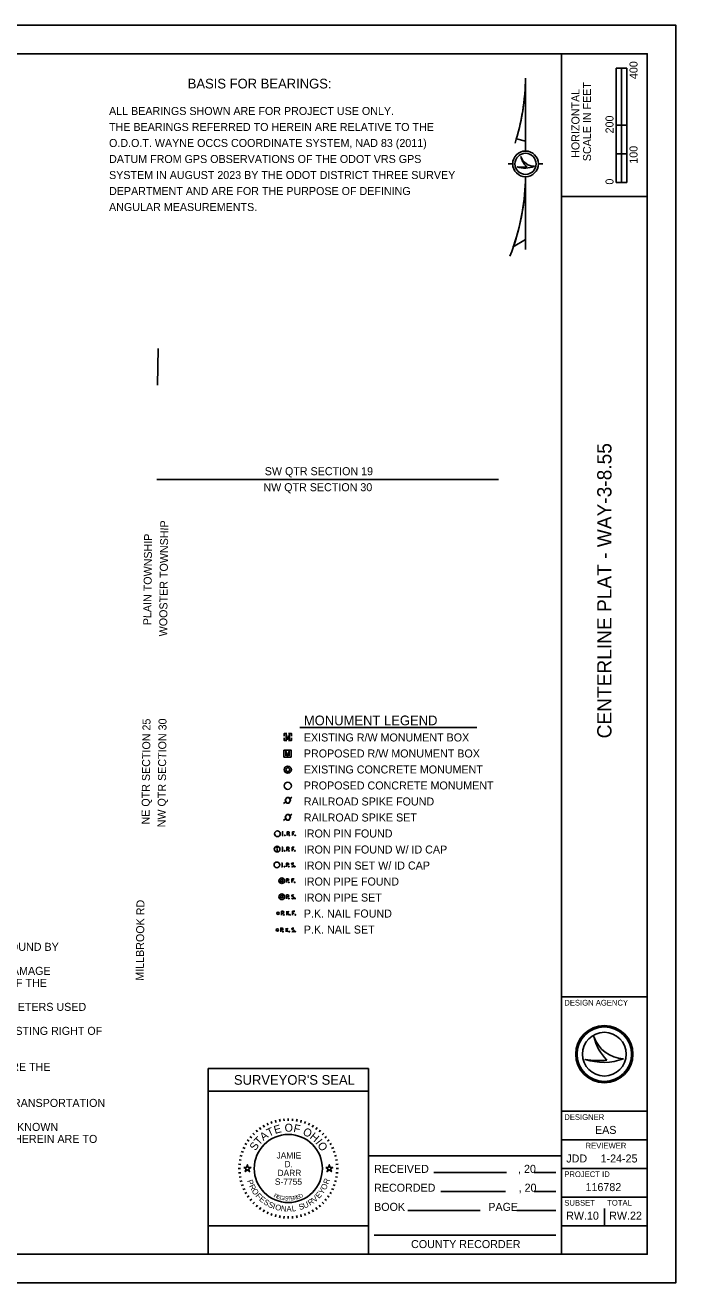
# Model space of a CAD drawing. Extents: x 132828 to 139628, y 472735 to 477135.
# Drawn here: x 137353 to 139628, y 472735 to 477135 of the extents above; entities that cross this region are included whole.
import ezdxf

# ---------------------------------------------------------------- set-up
doc = ezdxf.new("R2010")
doc.units = 0
for name, color, linetype in [('_CIVIL_CONSTRUCTION', 7, 'Continuous'), ('Default', 7, 'Continuous'), ('GE_X_Alignment', 7, 'Continuous'), ('GE_X_Alignment_100_Bearings', 7, 'Continuous'), ('GE_X_Alignment_100_Cardinal_Points', 7, 'Continuous'), ('GE_X_Alignment_100_Stations', 7, 'Continuous')]:
    doc.layers.add(name, color=color, linetype=linetype)

msp = doc.modelspace()

# ---------------------------------------------------------------- linework, layer by layer
at = {"layer": '_CIVIL_CONSTRUCTION'}
msp.add_lwpolyline([(132828.1, 472735.2), (139628.1, 472735.2), (139628.1, 477135.2), (132828.1, 477135.2)], close=True, dxfattribs=at)
at = {"layer": 'Default'}
for p, q in [((138257.6, 473309.5), (138258.3, 473301.5)), ((138272.9, 473310.2), (138272.9, 473302.2)), ((138288.1, 473309.5), (138287.4, 473301.5)), ((138160.4, 473269.2), (138165.5, 473263.1)), ((138172.5, 473278.5), (138177.1, 473272)), ((138185.4, 473286.7), (138189.4, 473279.8)), ((138198.9, 473293.8), (138202.3, 473286.5)), ((138213, 473299.6), (138215.8, 473292.1)), ((138227.6, 473304.2), (138229.7, 473296.5)), ((138242.5, 473307.5), (138243.9, 473299.6)), ((138303.3, 473307.5), (138301.9, 473299.6)), ((138318.2, 473304.2), (138316.1, 473296.5)), ((138332.7, 473299.6), (138330, 473292.1)), ((138346.9, 473293.8), (138343.5, 473286.5)), ((138360.4, 473286.7), (138356.4, 473279.8)), ((138373.3, 473278.5), (138368.7, 473272)), ((138385.4, 473269.2), (138380.2, 473263.1)), ((138121.3, 473222.7), (138128.3, 473218.7)), ((138129.5, 473235.5), (138136.1, 473231)), ((138138.8, 473247.7), (138145, 473242.5)), ((138149.1, 473258.9), (138154.8, 473253.3)), ((138396.6, 473258.9), (138391, 473253.3)), ((138407, 473247.7), (138400.8, 473242.5)), ((138416.2, 473235.5), (138409.7, 473231)), ((138424.4, 473222.7), (138417.5, 473218.7)), ((138103.9, 473180.5), (138111.6, 473178.4)), ((138108.4, 473195), (138116, 473192.3)), ((138114.3, 473209.1), (138121.5, 473205.7)), ((138431.5, 473209.1), (138424.2, 473205.7)), ((138437.3, 473195), (138429.8, 473192.3)), ((138441.9, 473180.5), (138434.2, 473178.4)), ((138097.9, 473135.2), (138105.9, 473135.2)), ((138098.6, 473150.4), (138106.5, 473149.7)), ((138100.6, 473165.6), (138108.4, 473164.2)), ((138445.2, 473165.6), (138437.4, 473164.2)), ((138447.2, 473150.4), (138439.3, 473149.7)), ((138447.9, 473135.2), (138439.9, 473135.2)), ((138098.6, 473119.9), (138106.5, 473120.6)), ((138100.6, 473104.8), (138108.4, 473106.2)), ((138103.9, 473089.9), (138111.6, 473091.9)), ((138441.9, 473089.9), (138434.2, 473091.9)), ((138445.2, 473104.8), (138437.4, 473106.2)), ((138447.2, 473119.9), (138439.3, 473120.6)), ((138108.4, 473075.3), (138116, 473078)), ((138114.3, 473061.2), (138121.5, 473064.6)), ((138121.3, 473047.7), (138128.3, 473051.7)), ((138424.4, 473047.7), (138417.5, 473051.7)), ((138431.5, 473061.2), (138424.2, 473064.6)), ((138437.3, 473075.3), (138429.8, 473078)), ((138129.5, 473034.8), (138136.1, 473039.4)), ((138138.8, 473022.7), (138145, 473027.8)), ((138149.1, 473011.4), (138154.8, 473017.1)), ((138160.4, 473001.1), (138165.5, 473007.2)), ((138385.4, 473001.1), (138380.2, 473007.2)), ((138396.6, 473011.4), (138391, 473017.1)), ((138407, 473022.7), (138400.8, 473027.8)), ((138416.2, 473034.8), (138409.7, 473039.4)), ((138172.5, 472991.8), (138177.1, 472998.4)), ((138185.4, 472983.6), (138189.4, 472990.5)), ((138198.9, 472976.6), (138202.3, 472983.8)), ((138213, 472970.7), (138215.8, 472978.2)), ((138227.6, 472966.1), (138229.7, 472973.9)), ((138242.5, 472962.8), (138243.9, 472970.7)), ((138257.6, 472960.8), (138258.3, 472968.8)), ((138272.9, 472960.2), (138272.9, 472968.2)), ((138288.1, 472960.8), (138287.4, 472968.8)), ((138303.3, 472962.8), (138301.9, 472970.7)), ((138318.2, 472966.1), (138316.1, 472973.9)), ((138332.7, 472970.7), (138330, 472978.2)), ((138346.9, 472976.6), (138343.5, 472983.8)), ((138360.4, 472983.6), (138356.4, 472990.5)), ((138373.3, 472991.8), (138368.7, 472998.4))]:
    msp.add_line(p, q, dxfattribs=at)
for points in [[(138117.6, 473139.2), (138127, 473139.2), (138129.9, 473148.1), (138132.8, 473139.2), (138142.2, 473139.2), (138134.6, 473133.6), (138137.5, 473124.7), (138129.9, 473130.2), (138122.3, 473124.7), (138125.2, 473133.6)], [(138403.6, 473139.2), (138413, 473139.2), (138415.9, 473148.1), (138418.8, 473139.2), (138428.2, 473139.2), (138420.6, 473133.6), (138423.5, 473124.7), (138415.9, 473130.2), (138408.3, 473124.7), (138411.2, 473133.6)]]:
    msp.add_lwpolyline(points, close=True, dxfattribs=at)
msp.add_circle((138272.9, 473135.2), 119, dxfattribs=at)
at = {"layer": 'GE_X_Alignment'}
for p, q in [((138313.4, 474678.2), (138931.9, 474678.2)), ((138271, 474644.9), (138271, 474644.9)), ((138270, 474586.8), (138270, 474586.8)), ((138264.3, 474418.5), (138256.3, 474412.5)), ((138285.7, 474434.5), (138277.7, 474428.5)), ((138285.7, 474375.1), (138277.7, 474369.1)), ((138264.3, 474359.1), (138256.3, 474353.2)), ((138251.3, 474313), (138254.6, 474313)), ((138251.3, 474313), (138254.6, 474313)), ((138251.3, 474299.7), (138254.6, 474299.7)), ((138252.9, 474299.7), (138252.9, 474313)), ((138268.3, 474306.6), (138273.6, 474306.6)), ((138287, 474299.7), (138287, 474313)), ((138287, 474313), (138294.7, 474313)), ((138287, 474306.5), (138292.5, 474306.5)), ((138233.8, 474253.5), (138233.8, 474246.1)), ((138250.4, 474259.2), (138253.8, 474259.2)), ((138250.4, 474259.2), (138253.8, 474259.2)), ((138250.4, 474245.8), (138253.8, 474245.8)), ((138252.1, 474245.8), (138252.1, 474259.2)), ((138267.4, 474252.8), (138272.8, 474252.8)), ((138286.2, 474245.8), (138286.2, 474259.2)), ((138286.2, 474259.2), (138293.8, 474259.2)), ((138286.2, 474252.7), (138291.6, 474252.7)), ((138249.6, 474203.9), (138252.9, 474203.9)), ((138249.6, 474203.9), (138252.9, 474203.9)), ((138249.6, 474190.5), (138252.9, 474190.5)), ((138251.2, 474190.5), (138251.2, 474203.9)), ((138266.6, 474197.5), (138271.9, 474197.5)), ((138285.4, 474199.1), (138291.5, 474196)), ((138285.5, 474135.4), (138285.5, 474148.7)), ((138285.5, 474148.7), (138293.2, 474148.7)), ((138266.8, 474142.3), (138272.1, 474142.3)), ((138285.5, 474142.2), (138291, 474142.2)), ((138266.8, 474086.1), (138272.1, 474086.1)), ((138285.7, 474087.7), (138291.8, 474084.5)), ((138249.2, 474028.6), (138254.5, 474028.6)), ((138267.9, 474021.7), (138267.9, 474035)), ((138267.9, 474026.5), (138274.3, 474035)), ((138269.9, 474029.3), (138275.4, 474021.7)), ((138287.5, 474021.7), (138287.5, 474035)), ((138287.5, 474035), (138295.2, 474035)), ((138287.5, 474028.5), (138293, 474028.5)), ((138246.3, 473970), (138251.7, 473970)), ((138264.9, 473963.1), (138264.9, 473976.4)), ((138264.9, 473967.9), (138271.3, 473976.4)), ((138266.9, 473970.7), (138272.4, 473963.1)), ((138286, 473971.8), (138292.1, 473968.6)), ((138552.9, 472835.2), (138552.9, 473180)), ((138552.9, 473180), (139228.1, 473180)), ((139228.1, 473180), (139228.1, 472835.2)), ((138781.4, 473121), (139035.9, 473121)), ((139132.6, 473121), (139208.1, 473121)), ((138806.5, 473054.3), (139032.7, 473054.3)), ((139132.6, 473054.3), (139208.1, 473054.3)), ((138690.8, 472987.7), (138944, 472987.7)), ((139072, 472987.7), (139208.1, 472987.7)), ((138572.9, 472902), (139208.1, 472902))]:
    msp.add_line(p, q, dxfattribs=at)
for points in [[(138258.5, 474648.1), (138258.5, 474657.4), (138267.8, 474657.4)], [(138267.8, 474632.4), (138258.5, 474632.4), (138258.5, 474641.8)], [(138264.8, 474636.6), (138264.8, 474653.2), (138271, 474636.6), (138277.1, 474653.2), (138277.1, 474636.6)], [(138273.9, 474657.4), (138283.5, 474657.4), (138283.5, 474648.1)], [(138283.5, 474641.8), (138283.5, 474632.4), (138273.9, 474632.4)], [(138257.5, 474599.3), (138282.6, 474599.3), (138282.6, 474574.3), (138257.5, 474574.3), (138257.5, 474599.3)], [(138263.9, 474578.5), (138263.9, 474595.1), (138270, 474578.5), (138276.2, 474595.1), (138276.2, 474578.5)], [(138273.6, 474313), (138268.3, 474313), (138268.3, 474299.7)], [(138272.8, 474259.2), (138267.4, 474259.2), (138267.4, 474245.8)], [(138271.9, 474203.9), (138266.6, 474203.9), (138266.6, 474190.5)], [(138272.1, 474148.7), (138266.8, 474148.7), (138266.8, 474135.4)], [(138272.1, 474092.4), (138266.8, 474092.4), (138266.8, 474079.1)], [(138254.5, 474035), (138249.2, 474035), (138249.2, 474021.7)], [(138251.7, 473976.4), (138246.3, 473976.4), (138246.3, 473963.1)]]:
    msp.add_lwpolyline(points, dxfattribs=at)
for points in [[(138267.2, 474433.5), (138274.7, 474433.5), (138280.6, 474423.5), (138274.7, 474413.5), (138267.2, 474413.5), (138261.3, 474423.5)], [(138267.2, 474374.1), (138274.7, 474374.1), (138280.6, 474364.1), (138274.7, 474354.1), (138267.2, 474354.1), (138261.3, 474364.1)]]:
    msp.add_lwpolyline(points, close=True, dxfattribs=at)
for centre, radius in [((138271, 474530.4), 12.5), ((138271, 474530.4), 6.67), ((138271, 474474.1), 12.5), ((138234.6, 474306.3), 10), ((138261, 474300.6), 1.17), ((138276.3, 474300.6), 1.17), ((138296.6, 474300.6), 1.17), ((138233.8, 474252.5), 10), ((138233.8, 474257.9), 1.33), ((138260.1, 474246.7), 1.17), ((138275.4, 474246.7), 1.17), ((138295.8, 474246.7), 1.17), ((138232.9, 474197.2), 10), ((138259.3, 474191.4), 1.17), ((138274.6, 474191.4), 1.17), ((138296, 474191.4), 1.17), ((138250.1, 474142.1), 10), ((138250.1, 474142.1), 4.12), ((138274.8, 474136.3), 1.17), ((138295.2, 474136.3), 1.17), ((138250.1, 474085.8), 10), ((138250.1, 474085.8), 4.17), ((138274.8, 474080), 1.17), ((138296.2, 474079.9), 1.17), ((138237.2, 474028.3), 4.15), ((138257.2, 474022.6), 1.17), ((138279.1, 474022.6), 1.17), ((138297.2, 474022.6), 1.17), ((138234.6, 473969.8), 4.12), ((138254.3, 473964), 1.17), ((138276.6, 473964), 1.17), ((138296.6, 473964), 1.17)]:
    msp.add_circle(centre, radius, dxfattribs=at)
for centre, radius, start, end in [((138273.1, 474309.8), 3.24, 278.8803, 81.1197), ((138272.3, 474256), 3.24, 278.8803, 81.1197), ((138271.4, 474200.7), 3.24, 278.8803, 81.1197), ((138286.7, 474201.1), 2.37, 126.2587, 236.3675), ((138288.4, 474196.1), 5.53, 223.6695, 304.3963), ((138288.7, 474196.9), 6.99, 61.3463, 118.6537), ((138289.5, 474193.8), 2.96, 311.4883, 47.9358), ((138271.6, 474145.5), 3.24, 278.8803, 81.1197), ((138271.6, 474089.2), 3.24, 278.8803, 81.1197), ((138287, 474089.7), 2.37, 126.2587, 236.3675), ((138288.6, 474084.7), 5.53, 223.6695, 304.3963), ((138288.9, 474085.4), 6.99, 61.3463, 118.6537), ((138289.8, 474082.3), 2.96, 311.4883, 47.9358), ((138254, 474031.8), 3.24, 278.8803, 81.1197), ((138251.2, 473973.2), 3.24, 278.8803, 81.1197), ((138287.3, 473973.7), 2.37, 126.2587, 236.3675), ((138289.3, 473969.5), 6.99, 61.3463, 118.6537), ((138290.1, 473966.4), 2.96, 311.4883, 47.9358), ((138289, 473968.7), 5.53, 223.6695, 304.3963)]:
    msp.add_arc(centre, radius, start, end, dxfattribs=at)
at = {"layer": 'GE_X_Alignment_100_Bearings'}
for p, q in [((139419.5, 476585.2), (139419.5, 476985.2)), ((139457, 476985.2), (139419.5, 476985.2)), ((139419.5, 476785.2), (139419.5, 476985.2)), ((139419.5, 476985.2), (139438.1, 476985.2)), ((139438.1, 476985.2), (139438.3, 476985.2)), ((139438.3, 476985.2), (139438.3, 476785.2)), ((139457, 476985.2), (139457, 476585.2)), ((139102.5, 476694.8), (139102.5, 476949.8)), ((139438.3, 476785.2), (139419.5, 476785.2)), ((139456.8, 476785.2), (139438.1, 476785.2)), ((139438.1, 476785.2), (139438.1, 476685.2)), ((139456.8, 476685.2), (139456.8, 476785.2)), ((139070.6, 476737.9), (139102.5, 476729.2)), ((139438.1, 476685.2), (139419.5, 476685.2)), ((139419.5, 476685.2), (139419.5, 476585.2)), ((139438.1, 476685.2), (139456.8, 476685.2)), ((139438.1, 476585.2), (139438.1, 476685.2)), ((139041.5, 476649.8), (139057.5, 476649.8)), ((139147.5, 476649.8), (139163.5, 476649.8)), ((139102.5, 476349.8), (139102.5, 476604.8)), ((139457, 476585.2), (139419.5, 476585.2)), ((139419.5, 476585.2), (139438.1, 476585.2)), ((139102.5, 476384.8), (139059.6, 476359.1)), ((139341.6, 473597.1), (139341.6, 473597.1)), ((139378.1, 473535.2), (139378.1, 473535.2)), ((138552.9, 473485.2), (137992.9, 473485.2)), ((137992.9, 473485.2), (137992.9, 472835.2)), ((138552.9, 472835.2), (138552.9, 473485.2)), ((139311.6, 473517.1), (139311.6, 473517.1)), ((139445.6, 473518.9), (139445.6, 473518.9)), ((138552.9, 473405.2), (137992.9, 473405.2)), ((139378.1, 472935.2), (139378.1, 472995.2)), ((138552.9, 472835.2), (137992.9, 472835.2))]:
    msp.add_line(p, q, dxfattribs=at)
for points in [[(139070.4, 476738), (139070.6, 476737.9), (139102.5, 476729.2), (139102.5, 476949.8)], [(139059.6, 476359.1), (139102.5, 476384.8), (139102.5, 476604.8)]]:
    msp.add_lwpolyline(points, dxfattribs=at)
msp.add_lwpolyline([(138552.9, 472835.2), (138552.9, 472935.2), (137992.9, 472935.2), (137992.9, 472835.2)], close=True, dxfattribs=at)
for centre, radius in [((139102.5, 476649.8), 45), ((139102.5, 476649.8), 37), ((139378.1, 473535.2), 100), ((139378.1, 473535.2), 95.4), ((139378.1, 473535.2), 95.4), ((139378.1, 473535.2), 76.4)]:
    msp.add_circle(centre, radius, dxfattribs=at)
for centre, radius, start, end in [((138314.1, 476960.9), 788.5, 342.4153, 359.1947), ((138314.1, 476960.9), 788.5, 343.5754, 359.1947), ((139134, 476692.4), 51, 199.1575, 269.3709), ((139155.8, 476691.6), 71.7, 192.8556, 227.3141), ((139100.3, 476725.6), 90.5, 252.4874, 291.486), ((139091.5, 476752.1), 114.3, 260.7277, 277.8734), ((138314.1, 476615.9), 788.5, 338.5054, 359.1947), ((138314.1, 476615.9), 788.5, 340.9936, 359.1947), ((139451.3, 473634.7), 116, 198.9257, 198.9319), ((139497.5, 473629.2), 159.1, 191.6379, 191.6421), ((139451.3, 473634.7), 116, 198.9319, 267.1657), ((139497.5, 473629.2), 159.1, 191.6421, 226.0947), ((139376, 473709.2), 202.6, 251.4576, 290.0832), ((139357.7, 473766), 253.2, 259.4964, 259.4995), ((139376, 473709.2), 202.6, 251.4527, 251.4576), ((139357.7, 473766), 253.2, 259.4995, 276.6672)]:
    msp.add_arc(centre, radius, start, end, dxfattribs=at)
at = {"layer": 'GE_X_Alignment_100_Cardinal_Points'}
for p, q in [((139228.1, 472835.2), (139228.1, 477035.2)), ((139228.1, 476535.2), (139528.1, 476535.2)), ((139228.1, 473735.2), (139528.1, 473735.2)), ((139228.1, 473335.2), (139528.1, 473335.2)), ((139228.1, 473235.2), (139528.1, 473235.2)), ((139228.1, 473135.2), (139528.1, 473135.2)), ((139228.1, 473035.2), (139528.1, 473035.2)), ((139228.1, 472935.2), (139528.1, 472935.2))]:
    msp.add_line(p, q, dxfattribs=at)
msp.add_lwpolyline([(133128.1, 477035.2), (139528.1, 477035.2), (139528.1, 472835.2), (133128.1, 472835.2)], close=True, dxfattribs=at)
at = {"layer": 'GE_X_Alignment_100_Stations'}
for p, q in [((137815.9, 475875.5), (137817.2, 476003.5)), ((137812.6, 475545.5), (139007.4, 475545.5))]:
    msp.add_line(p, q, dxfattribs=at)

# ---------------------------------------------------------------- texts
at = {"layer": 'Default'}
for s, height, p in [('UNDERGROUND UTILITY LOCATIONS ARE SHOWN FOR INFORMATION PURPOSES ONLY. THEIR LOCATION AS MARKED ON THE GROUND BY ', 28, (134905, 473896.7)), ('B319100735-00B AND B319100742-00B WERE SURVEYED AND MAPPED AS PART OF THIS PROJECT. I FOLLOWED OHIO811 UTILITY DAMAGE', 28, (134905, 473812.7)), ('PREVENTION LAWS AND HAVE NO DIRECT KNOWLEDGE OR CONTROL OF HOW THESE MARKS WERE PLACED, NOR KNOWLEDGE OF THE ', 28, (134905, 473770.7)), ('SEE THE AFFIXED SURVEY PARAMETERS NOTE ON THE CENTERLINE PLATS FOR THE HORIZONTAL AND VERTICAL SURVEY PARAMETERS USED ', 28, (134905, 473686.7)), ('AS PART OF THIS PROJECT I HAVE REESTABLISHED THE LOCATIONS OF THE EXISTING BOUNDARY LINES AND CENTERLINE OF EXISTING RIGHT OF ', 28, (134905, 473602.7)), ('ROAD OCCUPIED (PRO), NET TAKE, AND NET RESIDUE; AS WELL AS PREPARED THE LEGAL DESCRIPTIONS NECESSARY TO ACQUIRE THE', 28, (134905, 473476.7)), ('UNDERSTANDING BETWEEN THE BOARD OF REGISTRATION FOR ENGINEERS AND SURVEYORS AND THE OHIO DEPARTMENT OF TRANSPORTATION ', 28, (134905, 473350.7)), ('ALL OF MY WORK CONTAINED HEREIN WAS CONDUCTED IN ACCORDANCE WITH OHIO ADMINISTRATIVE CODE 4733-37 COMMONLY KNOWN', 28, (134905, 473266.7)), ('AS "MINIMUM STANDARDS FOR BOUNDARY SURVEYS IN THE STATE OF OHIO" UNLESS SO NOTED. THE WORDS I AND MY AS USED HEREIN ARE TO', 28, (134905, 473224.7)), ('JAMIE', 22, (138231.6, 473170.1)), ('D.', 22, (138259.5, 473139.5)), ('S-7755', 22, (138225.8, 473078.2)), ('DARR', 22, (138235.1, 473108.8))]:
    msp.add_text(s, height=height, dxfattribs=at).set_placement(p)
for s, height, rotation, p in [('T', 28, 25.7167, (138205.2, 473245.5)), ('E', 28, 15.7571, (138226.6, 473255.9)), ('O', 28, 359.7812, (138259.8, 473264)), ('F', 28, 347.4362, (138289.1, 473263.5)), ('O', 28, 332.2586, (138320.9, 473255.5)), ('S', 28, 57.1924, (138158.5, 473195.5)), ('T', 28, 46.4344, (138170.6, 473214.5)), ('A', 28, 36.4747, (138185.6, 473230.8)), ('H', 28, 319.9136, (138345.5, 473242.4)), ('I', 28, 308.367, (138366.2, 473224.8)), ('O', 28, 303.1491, (138373.3, 473216.9)), ('P', 20, 289.7431, (138128, 473092)), ('R', 20, 70.983, (138413.1, 473078.5)), ('R', 20, 296.9802, (138134.7, 473073.7)), ('O', 20, 304.7158, (138143.5, 473056.7)), ('F', 20, 312.956, (138156.7, 473038.3)), ('R', 14, 334.487, (138220.4, 473036.2)), ('D', 14, 23.3052, (138313.1, 473030.6)), ('E', 20, 48.2687, (138380.2, 473028.6)), ('Y', 20, 55.5058, (138392.9, 473043.2)), ('O', 20, 62.7428, (138402.9, 473057.8)), ('E', 20, 319.6885, (138169, 473025.2)), ('S', 20, 326.9255, (138184, 473012.9)), ('S', 20, 334.1626, (138200.1, 473002.6)), ('I', 20, 341.3997, (138216.7, 472994.8)), ('O', 20, 345.1351, (138225.3, 472991.6)), ('E', 14, 341.04, (138231, 473031.2)), ('G', 14, 347.4752, (138241.2, 473027.5)), ('N', 20, 353.3752, (138246.1, 472986.3)), ('I', 14, 353.7858, (138254.7, 473024.5)), ('S', 14, 356.8926, (138260, 473023.7)), ('A', 20, 1.1108, (138266.7, 472984)), ('T', 14, 3.0061, (138270, 473022.9)), ('E', 14, 6.0117, (138280.7, 473023.4)), ('L', 20, 8.3479, (138286.2, 472984.5)), ('R', 14, 11.9184, (138291.4, 473024.6)), ('E', 14, 17.6836, (138302.9, 473027.2)), ('S', 20, 18.3234, (138313, 472989.4)), ('U', 20, 25.5604, (138329.6, 472994.9)), ('R', 20, 33.296, (138349.2, 473004.6)), ('V', 20, 41.0316, (138365.2, 473015.3))]:
    msp.add_text(s, height=height, rotation=rotation, dxfattribs=at).set_placement(p)
at = {"layer": 'GE_X_Alignment'}
for s, height, p in [('BASIS FOR BEARINGS:', 34, (137921.1, 476913.7)), ('ALL BEARINGS SHOWN ARE FOR PROJECT USE ONLY.', 28, (137646, 476820.9)), ('THE BEARINGS REFERRED TO HEREIN ARE RELATIVE TO THE ', 28, (137646, 476764.9)), ('O.D.O.T. WAYNE OCCS COORDINATE SYSTEM, NAD 83 (2011)', 28, (137646, 476708.9)), ('DATUM FROM GPS OBSERVATIONS OF THE ODOT VRS GPS', 28, (137646, 476652.9)), ('SYSTEM IN AUGUST 2023 BY THE ODOT DISTRICT THREE SURVEY', 28, (137646, 476596.9)), ('DEPARTMENT AND ARE FOR THE PURPOSE OF DEFINING', 28, (137646, 476540.9)), ('ANGULAR MEASUREMENTS.', 28, (137646, 476484.9)), ('SW QTR SECTION 19', 28, (138190.5, 475560.7)), ('NW QTR SECTION 30', 28, (138185.8, 475504.7)), ('MONUMENT LEGEND', 34, (138327.2, 474685.8)), ('EXISTING R/W MONUMENT BOX', 28, (138327.2, 474629.2)), ('PROPOSED R/W MONUMENT BOX', 28, (138327.2, 474573.2)), ('EXISTING CONCRETE MONUMENT', 28, (138327.2, 474517.2)), ('PROPOSED CONCRETE MONUMENT', 28, (138327.2, 474461.2)), ('RAILROAD SPIKE FOUND', 28, (138327.2, 474405.2)), ('RAILROAD SPIKE SET', 28, (138327.2, 474349.2)), ('IRON PIN FOUND', 28, (138327.2, 474293.2)), ('IRON PIN FOUND W/ ID CAP', 28, (138327.2, 474237.2)), ('IRON PIN SET W/ ID CAP', 28, (138327.2, 474181.2)), ('IRON PIPE FOUND', 28, (138327.2, 474125.2)), ('IRON PIPE SET', 28, (138327.2, 474069.2)), ('P.K. NAIL FOUND', 28, (138327.2, 474013.2)), ('P.K. NAIL SET', 28, (138327.2, 473957.2)), ('RECEIVED                              , 20', 28, (138572.9, 473120)), ('RECORDED                            , 20', 28, (138572.9, 473054)), ('BOOK                            PAGE', 28, (138572.9, 472987)), ('COUNTY RECORDER', 28, (138702.2, 472856.8))]:
    msp.add_text(s, height=height, dxfattribs=at).set_placement(p)
for s, p in [('WOOSTER TOWNSHIP', (137849.1, 474996.9)), ('PLAIN TOWNSHIP', (137793.5, 475035.8)), ('NE QTR SECTION 25', (137787.4, 474338.6)), ('NW QTR SECTION 30', (137843.3, 474328.7)), ('MILLBROOK RD', (137767.1, 473792.1))]:
    msp.add_text(s, height=28, rotation=89.4281, dxfattribs=at).set_placement(p)
at = {"layer": 'GE_X_Alignment_100_Bearings'}
for s, height, p in [('400', 28, (139494.2, 476946.5)), ('SCALE IN FEET', 28, (139331.6, 476659.3)), ('HORIZONTAL', 28, (139291.1, 476671)), ('200', 28, (139410.2, 476756.5)), ('100', 28, (139494.2, 476650.5)), ('0', 28, (139410.2, 476577.4)), ('CENTERLINE PLAT - WAY-3-8.55', 50, (139403.1, 474640))]:
    msp.add_text(s, height=height, rotation=90, dxfattribs=at).set_placement(p)
for s, height, p in [('DESIGN AGENCY', 20, (139238.1, 473705.2)), ("SURVEYOR'S SEAL", 34, (138082.5, 473428.2)), ('DESIGNER', 20, (139238.1, 473305.2)), ('EAS', 28, (139345.5, 473256.2)), ('REVIEWER', 20, (139312.5, 473205.2)), ('JDD', 28, (139245, 473156.2)), ('1-24-25', 28, (139365, 473156.2)), ('PROJECT ID', 20, (139238.1, 473105.2)), ('116782', 28, (139312.3, 473056.2)), ('SUBSET', 20, (139238.1, 473005.2)), ('TOTAL', 20, (139388.1, 473005.2)), ('RW.10', 28, (139244.6, 472956.2)), ('RW.22', 28, (139395, 472956.2))]:
    msp.add_text(s, height=height, dxfattribs=at).set_placement(p)

doc.saveas('drawing.dxf')
